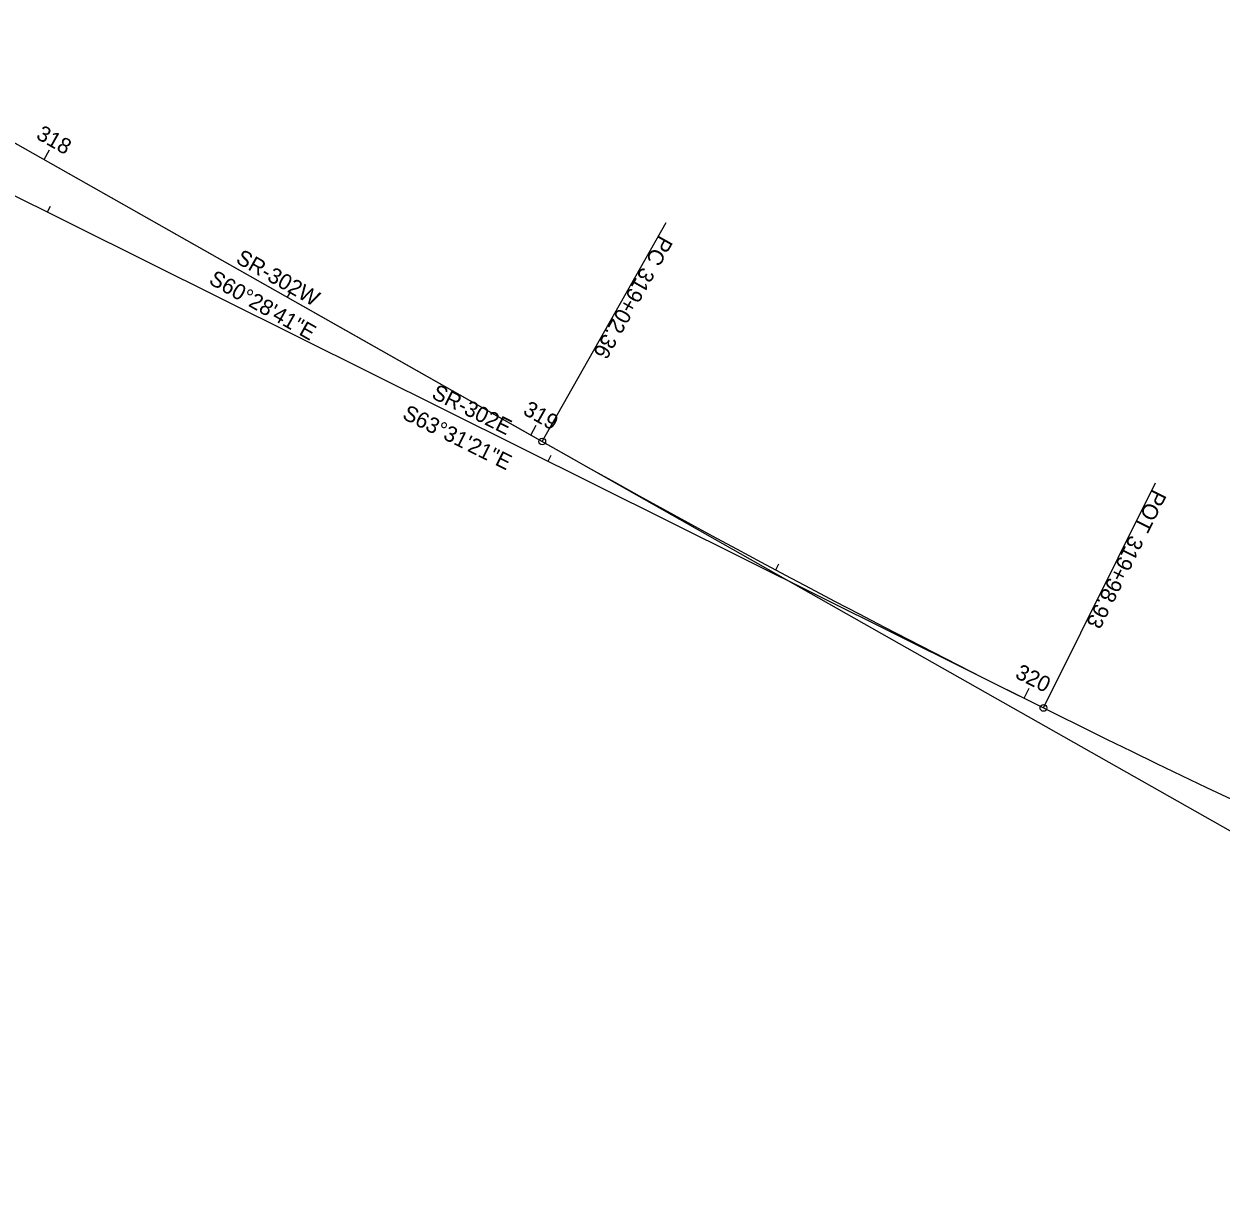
# Model space of a CAD drawing. Extents: x 2047151 to 2048731, y 456453 to 457874.
# Drawn here: x 2047891.2 to 2048105.2, y 456761.9 to 456969.4 of the extents above; entities that cross this region are included whole.
import ezdxf

# ---------------------------------------------------------------- set-up
doc = ezdxf.new("R2010")
doc.units = 0
for name, color, linetype in [('GE_P_Alignment', 7, 'Continuous'), ('GE_P_Alignment_100_Bearings', 7, 'Continuous'), ('GE_P_Alignment_100_Cardinal_Points', 7, 'Continuous'), ('GE_P_Alignment_100_Distances', 7, 'Continuous'), ('GE_P_Alignment_100_Stations', 7, 'Continuous'), ('GE_P_Alignment_500_Bearings', 7, 'Continuous'), ('GE_P_Alignment_500_Cardinal_Points', 7, 'Continuous'), ('GE_P_Alignment_500_Distances', 7, 'Continuous'), ('GE_P_Alignment_500_Stations', 7, 'Continuous')]:
    doc.layers.add(name, color=color, linetype=linetype)

msp = doc.modelspace()

# ---------------------------------------------------------------- linework, layer by layer
at = {"layer": 'GE_P_Alignment'}
for p, q in [((2047851.96, 456969.42), (2048122.29, 456816.34)), ((2047867.94, 456949.46), (2048073.45, 456847.09)), ((2047867.94, 456949.46), (2048073.45, 456847.09)), ((2047888.25, 456948.87), (2047983.86, 456894.73))]:
    msp.add_line(p, q, dxfattribs=at)
msp.add_arc((2048925.02, 458556.75), 1910, 240.47809, 250.00047, dxfattribs=at)
msp.add_arc((2048925.02, 458556.75), 1910, 240.47809, 250.00047, dxfattribs=at)
at = {"layer": 'GE_P_Alignment_100_Cardinal_Points'}
msp.add_line((2047983.86, 456894.73), (2048006.03, 456933.89), dxfattribs=at)
msp.add_circle((2047983.86, 456894.73), 0.6, dxfattribs=at)
at = {"layer": 'GE_P_Alignment_100_Stations'}
for p, q in [((2047894.78, 456945.17), (2047895.77, 456946.91)), ((2047938.29, 456920.54), (2047938.88, 456921.58)), ((2047981.8, 456895.9), (2047982.79, 456897.64)), ((2048025.6, 456871.78), (2048026.16, 456872.84)), ((2048070.01, 456848.81), (2048070.91, 456850.6))]:
    msp.add_line(p, q, dxfattribs=at)
at = {"layer": 'GE_P_Alignment_500_Cardinal_Points'}
msp.add_line((2048073.45, 456847.09), (2048093.52, 456887.37), dxfattribs=at)
msp.add_circle((2048073.45, 456847.09), 0.6, dxfattribs=at)
at = {"layer": 'GE_P_Alignment_500_Stations'}
for p, q in [((2047895.39, 456935.79), (2047895.92, 456936.86)), ((2047984.9, 456891.2), (2047985.43, 456892.28))]:
    msp.add_line(p, q, dxfattribs=at)

# ---------------------------------------------------------------- texts
at = {"layer": 'GE_P_Alignment_100_Bearings'}
msp.add_text('S60°28\'41"E', height=2.8, rotation=330.4781, dxfattribs=at).set_placement((2047924.05, 456923.08))
at = {"layer": 'GE_P_Alignment_100_Cardinal_Points'}
for s, p in [('PC', (2048004.88, 456931.76)), ('319+02.36', (2048001.67, 456926.09))]:
    msp.add_text(s, height=2.8, rotation=240.4781, dxfattribs=at).set_placement(p)
at = {"layer": 'GE_P_Alignment_100_Distances'}
msp.add_text('SR-302W', height=2.8, rotation=330.4781, dxfattribs=at).set_placement((2047928.88, 456926.81))
at = {"layer": 'GE_P_Alignment_100_Stations'}
for s, rotation, p in [('318', 330.4781, (2047893.19, 456949.01)), ('319', 330.4781, (2047980.23, 456899.72)), ('320', 333.407, (2048068.22, 456852.56))]:
    msp.add_text(s, height=2.8, rotation=rotation, dxfattribs=at).set_placement(p)
at = {"layer": 'GE_P_Alignment_500_Bearings'}
msp.add_text('S63°31\'21"E', height=2.8, rotation=333.5225, dxfattribs=at).set_placement((2047958.65, 456898.92))
at = {"layer": 'GE_P_Alignment_500_Cardinal_Points'}
for s, p in [('POT', (2048093.05, 456886.34)), ('319+98.93', (2048088.98, 456878.16))]:
    msp.add_text(s, height=2.8, rotation=243.5225, dxfattribs=at).set_placement(p)
at = {"layer": 'GE_P_Alignment_500_Distances'}
msp.add_text('SR-302E', height=2.8, rotation=333.5225, dxfattribs=at).set_placement((2047963.88, 456902.59))

doc.saveas('drawing.dxf')
